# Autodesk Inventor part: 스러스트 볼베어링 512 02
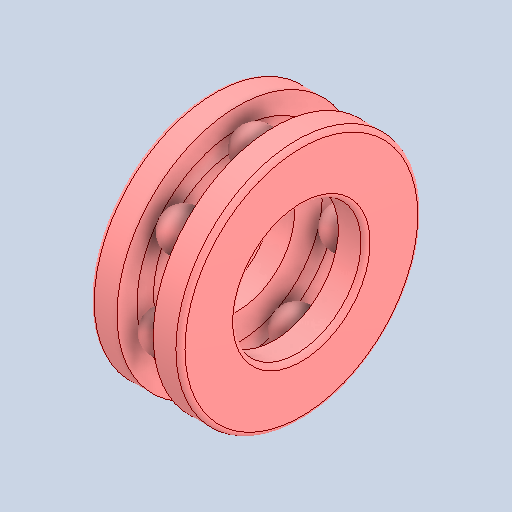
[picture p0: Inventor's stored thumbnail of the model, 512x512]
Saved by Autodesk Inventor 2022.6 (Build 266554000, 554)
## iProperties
Created: 2024-09
Part Number: 스러스트 볼베어링 512 02
Material: 강철, 연강
Description: 롤링 베어링 - 플랫 뒷면이 있는 스러스트 볼 베어링
Document SubType Name: Modeling
Designer: Class 001
Density: 7.85 g/cm^3
Appearance: 기본값
Author: jhkim
Sending System: Autodesk Inventor 2025
Preprocessor: ST-DEVELOPER v20
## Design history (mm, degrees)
feature "Solid1"
feature "Solid1:1"
feature "Solid1:2"
feature "Solid1:3"
feature "Solid1:4"
feature "Solid1:5"
feature "Solid1:6"
feature "Solid1:7"
feature "Solid1:8"
node "솔리드1"
node "솔리드2"
node "솔리드3"
node "솔리드4"
node "솔리드5"
node "솔리드6"
node "솔리드7"
node "솔리드8"
node "솔리드9"
